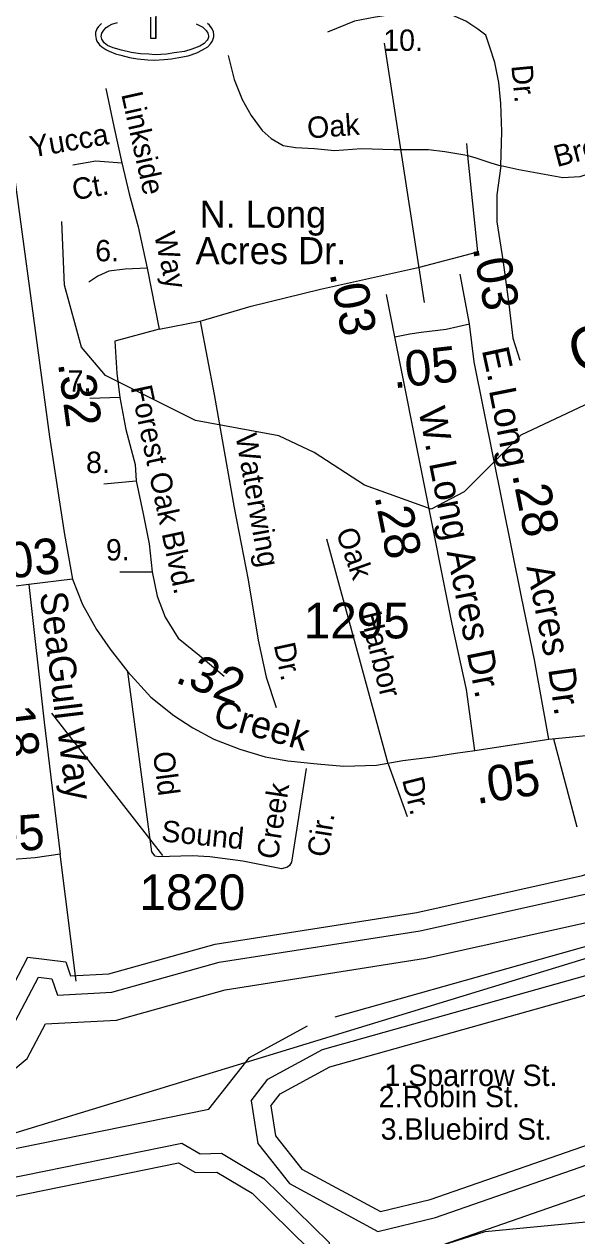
# Model space of a CAD drawing. Extents: x 2104537 to 2336408, y 34176 to 229611.
# Drawn here: x 2178229 to 2180170, y 55122 to 59376 of the extents above; entities that cross this region are included whole.
import ezdxf

# ---------------------------------------------------------------- set-up
doc = ezdxf.new("R2010")
doc.units = 0
for name, color, linetype in [('Exist Boundary Political City Limit New', 7, 'Continuous'), ('Exist Cultural Recreational Golf Course CELL', 7, 'Continuous'), ('Exist Hydrographic Buffer Line', 7, 'Continuous'), ('Exist Hydrographic Creek Single Shore', 7, 'Continuous'), ('Exist Hydrographic Island Shore', 7, 'Continuous'), ('Exist Road Non-System Type 51', 7, 'Continuous'), ('Exist Road Non-System Type 51 Label', 7, 'Continuous'), ('Exist Road Secondary Mileage Hundredths English Label', 7, 'Continuous'), ('Exist Road Secondary Type 51 Attributed', 7, 'Continuous'), ('Exist Road Secondary Type 51 Label', 7, 'Continuous'), ('Exist Road Secondary Type 51 Number Label', 7, 'Continuous'), ('Map Preparation Boundary City Limit Buffer Line', 7, 'Continuous'), ('Old_Level_32', 7, 'Continuous')]:
    doc.layers.add(name, color=color, linetype=linetype)

msp = doc.modelspace()

# ---------------------------------------------------------------- linework, layer by layer
at = {"layer": 'Exist Boundary Political City Limit New'}
msp.add_lwpolyline([(2185728, 55040.5), (2185856.2, 55203.8), (2185879.5, 55425.4), (2185949.5, 55635.4), (2186066, 55775.4), (2186322.2, 55938.7), (2186450.5, 56172), (2186520.5, 56673.6), (2186804.5, 56806.1), (2186790.2, 56814.1), (2186404.5, 56884.9), (2186089.8, 56872), (2185691.2, 56884.9), (2185389.2, 56839.8), (2184233.2, 56618.5), (2183988.8, 56567.1), (2182004, 56464.3), (2181271, 56421.4), (2178184.5, 55478.7), (2176257.8, 54846.6)], dxfattribs=at)
at = {"layer": 'Exist Cultural Recreational Golf Course CELL'}
for points in [[(2178692, 59425.4), (2178692, 59325.4), (2178673.6, 59325.4), (2178673.6, 59400.4)], [(2178692, 59400.4), (2178692, 59325.4), (2178692, 59400.4)], [(2178500.8, 59378.5), (2178490.6, 59367.5), (2178484.3, 59359.2), (2178480.3, 59347), (2178479.3, 59337.2), (2178482, 59322.7), (2178484.8, 59315.7), (2178493.8, 59303.4), (2178502.1, 59296.4), (2178516, 59286.8), (2178527.7, 59281), (2178550.3, 59271.5), (2178569, 59266.5), (2178599.3, 59259.2), (2178627.4, 59253.7), (2178663.8, 59250.4), (2178687.3, 59249.3), (2178721.1, 59251.4), (2178746.4, 59253.9), (2178772.8, 59258.5), (2178804.8, 59265), (2178835.9, 59275.5), (2178855.3, 59285.4), (2178873.8, 59296.7), (2178883.6, 59306.7), (2178889.6, 59314.9), (2178892.2, 59320.4), (2178893.6, 59324.5), (2178895, 59330.9), (2178895.8, 59337.7), (2178894.3, 59349), (2178889.8, 59359.2), (2178879.9, 59371.9), (2178873.7, 59378.6)], [(2178833.6, 59376.8), (2178856.3, 59365), (2178868.3, 59354.1), (2178873.8, 59344.5), (2178876.8, 59335), (2178876.5, 59330.6), (2178875.5, 59326.5), (2178874.5, 59323.2), (2178872.3, 59319.4), (2178861.6, 59307.6), (2178845.8, 59298), (2178818.5, 59287.6), (2178792, 59280.1), (2178756.4, 59274.6), (2178729.4, 59270.6), (2178689.3, 59268.7), (2178666.8, 59270.6), (2178637.7, 59272.1), (2178604.7, 59276.6), (2178570.7, 59284.1), (2178541.6, 59292.7), (2178522.1, 59301.2), (2178510.1, 59310.7), (2178501.6, 59322.7), (2178499.1, 59332.7), (2178501.6, 59343.7), (2178508.6, 59354.7), (2178517.1, 59364.3), (2178526.2, 59369.5), (2178537.6, 59375.3), (2178556.7, 59381.8)]]:
    msp.add_lwpolyline(points, dxfattribs=at)
at = {"layer": 'Exist Hydrographic Buffer Line'}
for points in [[(2176927.2, 55470.2), (2177032.4, 55390.7), (2178111, 55637.3), (2178240.1, 55743.8), (2178304.2, 55865.2), (2178553.3, 55878.8), (2178935.3, 55985.4), (2179639.1, 56095.7), (2180236.3, 56229), (2180465.6, 56311.7), (2180705.3, 56352.7), (2181638.5, 56673.5), (2182023.4, 56705.6), (2183248.1, 56645.9), (2183939.6, 56693.2), (2184682, 56816.8), (2185876.6, 57179.5), (2186229.1, 57507.2), (2186528.7, 57725.1), (2186735.7, 57982.2), (2186810.7, 58133.4)], [(2176435.4, 57166), (2176475.1, 57120.1), (2176515.9, 56898.7), (2176587, 56698.6), (2176738.1, 56392.2), (2176878.3, 55913.3), (2176888.6, 55725.9), (2176949.6, 55576.7), (2177055.2, 55496.9), (2178066.3, 55728.1), (2178162.3, 55807.2), (2178279.5, 56029.1), (2178326.9, 56023.5), (2178346.6, 55966.1), (2178537.2, 55976.5), (2178914.4, 56081.7), (2179620.7, 56192.5), (2180208.8, 56323.7), (2180440.4, 56407.2), (2180680.8, 56448.4), (2181618.1, 56770.6), (2182021.7, 56804.2), (2183247.2, 56744.5)], [(2179321.9, 55890.7), (2180687.1, 56273.6), (2181289, 56395.7), (2182436.1, 56554.4), (2182993.3, 56507.1)], [(2179208, 54702.7), (2179336.7, 54798), (2179613.7, 55061.3), (2179849.2, 55137), (2180605.2, 55208.5), (2181137.6, 55331.9), (2181752.1, 55524.2), (2182385.3, 55830.2), (2182808.2, 56006.1), (2183216.9, 56106.7), (2183541.1, 56130.2), (2183557.7, 56536.8)], [(2179026.1, 55595.8), (2179085.2, 55671), (2179277.7, 55776.1), (2180710.2, 56177.9), (2181305.6, 56298.6), (2182438.7, 56455.4), (2182871.6, 56418.6)], [(2178782.7, 55446.6), (2178847.3, 55409.5), (2178922.9, 55411.3), (2179070.8, 55323), (2179300.3, 55097.5), (2179286.5, 54978.5), (2179117.1, 54762.8), (2179085.9, 54670.2), (2178989.7, 54493.5), (2178788.2, 54400.5), (2178869.4, 54400.7), (2179191.6, 54568.1), (2179400.1, 54722.5), (2179665.2, 54974.5), (2179869.2, 55040), (2180621, 55111.2), (2181163.4, 55236.8), (2181788.4, 55432.4), (2182425.7, 55740.3), (2182839, 55912.3), (2183232.4, 56009.2), (2183584.6, 56034.7), (2183636.6, 56057.6), (2183652.4, 56443.4)], [(2178877.8, 55566.3), (2179020.3, 55747.7), (2179224.6, 55859.2)], [(2176134.9, 54746.5), (2176334.7, 54842.6), (2177545.4, 55175), (2178132.7, 55415.2), (2178877.8, 55566.3)], [(2179026.1, 55595.8), (2179050.4, 55445.2), (2179161.4, 55304.7), (2179471.5, 55136.5), (2179674, 55185.8), (2180259.7, 55389.4), (2180890.1, 55449.1), (2181201.5, 55530.9)], [(2176177.7, 54657.9), (2176369.4, 54750), (2177577.2, 55081.6), (2178161.4, 55320.6), (2178782.7, 55446.6)], [(2179701.9, 55091.3), (2180280.8, 55292.5), (2180907.4, 55351.9), (2181226.5, 55435.7)]]:
    msp.add_lwpolyline(points, dxfattribs=at)
at = {"layer": 'Exist Hydrographic Creek Single Shore'}
for points in [[(2183651.5, 58728.3), (2183369.6, 58559.9), (2183219.5, 58536.5), (2183061.6, 58569.1), (2182852.6, 58560), (2182427.6, 58614.1), (2182194.6, 58605.5), (2182028.5, 58562.8), (2181313.5, 58199.2), (2181180.4, 58182.1), (2180996.5, 58231.6), (2180788.6, 58229), (2180297.5, 58084.3), (2179973.5, 57933.1), (2179774.6, 57733.5), (2179658.5, 57673.4), (2179424.6, 57756.6), (2179248.4, 57871.6), (2179123.6, 57929.8), (2178831.6, 57984.6), (2178514.5, 58141.7), (2178430.5, 58241.7), (2178370.4, 58459.4), (2178361.4, 58682.7)], [(2177070.4, 55567.7), (2178036.6, 55788.6), (2178110.4, 55849.5), (2178242.4, 56099.6), (2178375.5, 56083.9), (2178392.5, 56034.3), (2178526.4, 56041.6), (2178900.5, 56145.9), (2179608.5, 56257), (2180190.4, 56386.8), (2180423.6, 56470.9), (2180664.5, 56512.2), (2181604.5, 56835.3), (2182020.5, 56869.9), (2183246.5, 56810.2), (2183920.5, 56856.3), (2184644.6, 56976.8), (2185792.7, 57325.5), (2186124.6, 57634), (2186414.6, 57845), (2186596.7, 58071.1), (2186683.1, 58245.3)], [(2176206.1, 54598.7), (2176392.5, 54688.3), (2177598.4, 55019.4), (2178180.5, 55257.5), (2178771.5, 55377.4)], [(2178771.5, 55377.4), (2178830.5, 55343.4), (2178905.6, 55345.3), (2179030.5, 55270.7), (2179231.4, 55073.2)]]:
    msp.add_lwpolyline(points, dxfattribs=at)
at = {"layer": 'Exist Hydrographic Island Shore'}
for points in [[(2179095.5, 55577.8), (2179128.5, 55619.9), (2179302.6, 55714.9), (2180725.6, 56114), (2181316.6, 56233.9), (2182440.5, 56389.4), (2182790.5, 56359.7)], [(2179095.5, 55577.8), (2179112.5, 55472.5), (2179204.5, 55355.9), (2179480.5, 55206.2), (2179655.5, 55248.8), (2180245.6, 55454), (2180878.6, 55513.9), (2181169.6, 55590.4)]]:
    msp.add_lwpolyline(points, dxfattribs=at)
at = {"layer": 'Exist Road Non-System Type 51'}
for p, q in [((2179788.2, 58914.5), (2179783.9, 58956.4)), ((2178660.9, 58519.6), (2178703.1, 58304.7)), ((2178703.1, 58304.7), (2178847.4, 58332.9)), ((2178565.8, 58065.2), (2178460.2, 58061.7)), ((2178509.5, 57762.3), (2178622.1, 57772.9)), ((2178565.8, 57452.4), (2178678.5, 57452.4)), ((2178411.5, 56015.6), (2178355.4, 56461.2))]:
    msp.add_line(p, q, dxfattribs=at)
for points in [[(2179903.6, 58878.9), (2179907.1, 58998.6), (2179903.6, 59097.2), (2179896.6, 59171.2), (2179882.5, 59241.7), (2179864.9, 59294.5), (2179850.8, 59336.8), (2179822.6, 59357.9), (2179780.4, 59386.1), (2179724, 59410.7), (2179667.7, 59421.3), (2179579.7, 59417.8), (2179463.5, 59400.2), (2179389.6, 59386.1), (2179294.5, 59347.3)], [(2178946, 59266.3), (2178967.1, 59181.8), (2178995.3, 59111.3), (2179027, 59055), (2179065.7, 59002.1), (2179097.4, 58974), (2179139.6, 58949.3), (2179181.9, 58942.3), (2179248.8, 58938.7), (2179319.2, 58931.7), (2179414.2, 58938.7), (2179526.9, 58935.2), (2179650.1, 58935.2), (2179706.4, 58928.2), (2179776.9, 58917.6), (2179788.2, 58914.5)], [(2178516.5, 59150.1), (2178544.7, 59016.2), (2178572.8, 58889.4)], [(2178400.3, 58882.4), (2178481.3, 58896.5), (2178572.8, 58889.4)], [(2178572.8, 58889.4), (2178597.5, 58780.2), (2178629.2, 58664), (2178646.8, 58583), (2178660.9, 58519.6)], [(2178847.4, 58332.9), (2179027, 58385.8), (2179269.9, 58445.6), (2179618.4, 58523.1), (2179822.6, 58576), (2179788.2, 58914.5)], [(2179788.2, 58914.5), (2179815.6, 58907), (2179868.4, 58889.4), (2179903.6, 58878.9)], [(2179903.6, 58878.9), (2179889.5, 58776.7), (2179889.5, 58681.6), (2179910.6, 58547.8), (2179931.8, 58392.8), (2179945.8, 58273), (2179970.5, 58195.5)], [(2180425.5, 58908.3), (2180368.3, 58896.5), (2180315.5, 58878.9), (2180234.5, 58857.7), (2180181.7, 58840.1), (2180121.9, 58836.6), (2180044.4, 58850.7), (2179967, 58864.8), (2179903.6, 58878.9)], [(2178660.9, 58519.6), (2178583.4, 58516.1), (2178527.1, 58509), (2178488.3, 58491.4), (2178456.7, 58470.3)], [(2178847.4, 58332.9), (2178896.7, 58075.8), (2178967.1, 57677.8), (2179016.4, 57424.2), (2179051.6, 57212.8), (2179079.8, 57082.5), (2179115, 56976.9)], [(2178703.1, 58304.7), (2178548.2, 58262.5), (2178555.2, 58149.8), (2178565.8, 58065.2)], [(2178565.8, 58065.2), (2178586.9, 57952.5), (2178618.6, 57829.2), (2178622.1, 57772.9)], [(2178622.1, 57772.9), (2178646.8, 57656.6), (2178667.9, 57551), (2178678.5, 57452.4)], [(2179508.4, 56778.9), (2179292.3, 57567.8)], [(2178678.5, 57452.4), (2178696.1, 57367.8), (2178724.2, 57293.9), (2178770, 57219.9), (2178843.9, 57160), (2178931.9, 57086)], [(2179219.5, 56762.8), (2179168.6, 56433.4), (2179161.1, 56421.7), (2179154.1, 56416.3), (2179133.3, 56410.1), (2178997.4, 56436.7), (2178881.8, 56451.7), (2178819.6, 56455.2), (2178699.7, 56452.3), (2178689.6, 56454.1), (2178677.5, 56470.1), (2178593.8, 57101.3)], [(2180088.7, 56866.2), (2180170.3, 56556.9)], [(2179508.4, 56778.9), (2179574.5, 56593.4)]]:
    msp.add_lwpolyline(points, dxfattribs=at)
at = {"layer": 'Exist Road Secondary Type 51 Attributed'}
for p, q in [((2179794.1, 58323.3), (2179760.7, 58498.4)), ((2179531.7, 58277.4), (2179502.1, 58426.2)), ((2178245.1, 57408.6), (2178125.4, 57393.5)), ((2178399, 57427.6), (2178245.1, 57408.6)), ((2179812.7, 56826), (2180071.8, 56865.6))]:
    msp.add_line(p, q, dxfattribs=at)
for points in [[(2178157.9, 59116), (2178318.7, 57927.2), (2178370.5, 57584.3), (2178399, 57427.6)], [(2179531.7, 58277.4), (2179583.8, 58288.3), (2179624.3, 58294.7), (2179711.2, 58304.6), (2179794.1, 58323.3)], [(2180071.8, 56865.6), (2180022.4, 57144.3), (2179975.8, 57364.5), (2179810.4, 58190.1), (2179794.1, 58323.3)], [(2179812.7, 56826), (2179782.6, 57039.7), (2179732.6, 57269.3), (2179531.7, 58277.4)], [(2180071.8, 56865.6), (2180238.3, 56881.6), (2180378.5, 56908.1), (2180463.9, 56929.4), (2180529.7, 56952.1), (2180612.6, 56985), (2180726.8, 57035.9), (2180880.2, 57111.4), (2181045.4, 57188.6), (2181105.5, 57223.2), (2181165.1, 57251.9), (2181284.7, 57294.9), (2181356.3, 57317.4), (2181480.3, 57348.5), (2181904.3, 57440.5), (2182238.7, 57511.1), (2182524.2, 57569.1), (2182680.4, 57598.2), (2182774.3, 57612), (2182923.6, 57620.3), (2183114.3, 57613.4), (2183679.5, 57553.9), (2183892.3, 57537.3)], [(2178245.1, 57408.6), (2178299.4, 56924.9), (2178355.4, 56461.2)], [(2178399, 57427.6), (2178434, 57338), (2178483.8, 57250.4), (2178531.4, 57180.9), (2178593.8, 57101.3), (2178674.1, 57012.7), (2178754.9, 56948.4), (2178821.3, 56904.8), (2178895.9, 56865.4), (2178987.1, 56830.2), (2179076.2, 56803.2), (2179155, 56788.7), (2179258.6, 56778.3), (2179351.9, 56770), (2179466.6, 56774.2), (2179559.8, 56790.8), (2179663.5, 56803.2), (2179744.3, 56815.6), (2179812.7, 56826)], [(2178355.4, 56461.2), (2178267.8, 56448.6), (2178081.2, 56434.1)]]:
    msp.add_lwpolyline(points, dxfattribs=at)
at = {"layer": 'Exist Road Secondary Type 51 Number Label'}
for p, q in [((2179635.8, 58398.4), (2179494.7, 59309.2)), ((2178325.5, 56956.7), (2178714.9, 56457.2))]:
    msp.add_line(p, q, dxfattribs=at)
at = {"layer": 'Map Preparation Boundary City Limit Buffer Line'}
msp.add_lwpolyline([(2185728, 55040.5), (2185856.2, 55203.8), (2185879.5, 55425.4), (2185949.5, 55635.4), (2186066, 55775.4), (2186322.2, 55938.7), (2186450.5, 56172), (2186520.5, 56673.6), (2186804.5, 56806.1), (2186790.2, 56814.1), (2186404.5, 56884.9), (2186089.8, 56872), (2185691.2, 56884.9), (2185389.2, 56839.8), (2184233.2, 56618.5), (2183988.8, 56567.1), (2182004, 56464.3), (2181271, 56421.4), (2178184.5, 55478.7), (2176257.8, 54846.6)], dxfattribs=at)

# ---------------------------------------------------------------- texts
at = {"layer": 'Exist Road Non-System Type 51 Label'}
for s, p in [('10.', (2179490.6, 59282.1)), ('6.', (2178478.8, 58543.2)), ('7.', (2178381.9, 58085.3)), ('8.', (2178446.5, 57799.8)), ('9.', (2178516.4, 57492.7)), ('1.Sparrow St.', (2179495, 55647.4)), ('2.Robin St.', (2179474.6, 55573)), ('3.Bluebird St.', (2179481.5, 55458.8))]:
    msp.add_text(s, height=75, dxfattribs=at).set_placement(p)
for s, rotation, p in [('Dr.', 275.438, (2179940.4, 59230.3)), ('Linkside ', 282.5229, (2178569.8, 59129.9)), ('Oak', 4.2381, (2179225.9, 58974.1)), ('Yucca ', 9.8709, (2178255.6, 58907.2)), ('Brook', 14.6278, (2180100.7, 58873.7)), ('Ct.', 9.8709, (2178404.4, 58757)), ('Way', 282.5229, (2178685.1, 58637.3)), ('Forest Oak Blvd.', 281.9706, (2178603, 58100.2)), ('Waterwing', 280.0321, (2178971.2, 57931.4)), ('Oak ', 289.648, (2179323.1, 57593)), ('Harbor', 283.8654, (2179409.3, 57304.1)), ('Dr.', 282.1948, (2179105.6, 57196.2)), ('Old', 277.5471, (2178681.1, 56817.5)), ('Creek', 81.2042, (2179119.8, 56440.2)), ('Dr.', 283.8654, (2179556.2, 56723.1)), ('Sound', 354.3823, (2178708.7, 56506.6)), ('Cir.', 81.2042, (2179296.5, 56447.7))]:
    msp.add_text(s, height=75, rotation=rotation, dxfattribs=at).set_placement(p)
at = {"layer": 'Exist Road Secondary Mileage Hundredths English Label'}
for s, rotation, p in [('.03', 280.7966, (2179804.3, 58591)), ('.03', 281.2683, (2179301.6, 58500.9)), ('.05', 6.5105, (2179527.5, 58096.8)), ('.32', 277.7031, (2178347.6, 58185.3)), ('.28', 281.332, (2179942.9, 57795)), ('.28', 281.2682, (2179459.3, 57718)), ('.03', 7.0429, (2178130.3, 57422.3)), ('.32', 338.8669, (2178755.5, 57066.1)), ('.18', 276.8891, (2178133.6, 57023.9)), ('.05', 8.6824, (2179818.9, 56637.3)), ('.05', 4.4495, (2178073.1, 56461.3))]:
    msp.add_text(s, height=125, rotation=rotation, dxfattribs=at).set_placement(p)
at = {"layer": 'Exist Road Secondary Type 51 Label'}
for s, p in [('N. Long', (2178845.3, 58661.1)), ('Acres Dr.', (2178831.1, 58533.1))]:
    msp.add_text(s, height=95, dxfattribs=at).set_placement(p)
for s, rotation, p in [('E.', 282.1987, (2179836.4, 58232)), ('Long', 281.332, (2179861, 58091.1)), ('W. Long Acres Dr.', 281.2681, (2179613.6, 58021.7)), ('Acres', 281.332, (2179993.3, 57470.2)), ('Sea ', 276.889, (2178284.2, 57378.6)), ('Gull', 276.889, (2178311.9, 57155.2)), ('Dr.', 278.0592, (2180069.8, 57111.6)), ('Creek', 344.2647, (2178888.2, 56915.7)), ('Way', 277.1672, (2178345.6, 56898.6))]:
    msp.add_text(s, height=95, rotation=rotation, dxfattribs=at).set_placement(p)
at = {"layer": 'Exist Road Secondary Type 51 Number Label'}
for s, p in [('1295', (2179211.7, 57219.1)), ('1820', (2178634.3, 56265.3))]:
    msp.add_text(s, height=125, dxfattribs=at).set_placement(p)
at = {"layer": 'Old_Level_32'}
msp.add_text('Goose', height=150, rotation=16.4218, dxfattribs=at).set_placement((2180167.7, 58147.1))

doc.saveas('drawing.dxf')
